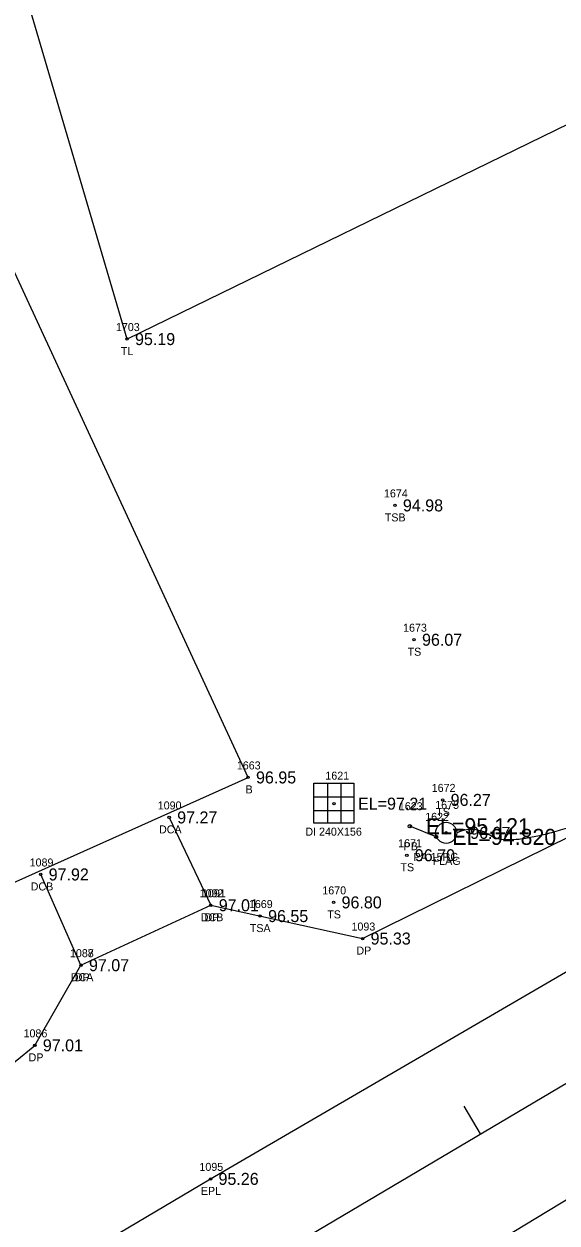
# Model space of a CAD drawing. Extents: x 2529517 to 2532038, y 935000 to 936944.
# Drawn here: x 2530845 to 2530911.6, y 935818.5 to 935968.4 of the extents above; entities that cross this region are included whole.
import ezdxf

# ---------------------------------------------------------------- set-up
doc = ezdxf.new("R2010")
doc.units = 0
for name, color, linetype in [('Default', 7, 'Continuous'), ('RD_DTM_BkLn_txCode', 7, 'Continuous'), ('RD_EX_Bldg', 7, 'Continuous'), ('RD_EX_Bldg_txCode', 7, 'Continuous'), ('RD_EX_BldgApp', 7, 'Continuous'), ('RD_EX_BldgApp_txCode', 7, 'Continuous'), ('RD_EX_Conc', 7, 'Continuous'), ('RD_EX_Conc_txCode', 7, 'Continuous'), ('RD_EX_DR_Inlet', 7, 'Continuous'), ('RD_EX_DR_Inlet_txCode', 7, 'Continuous'), ('RD_EX_DR_Pipe', 7, 'Continuous'), ('RD_EX_DR_Pipe_txCode', 7, 'Continuous'), ('RD_EX_Driveway', 7, 'Continuous'), ('RD_EX_Driveway_txCode', 7, 'Continuous'), ('RD_EX_Road', 7, 'Continuous'), ('RD_EX_Road_txCode', 7, 'Continuous'), ('RD_EX_TX_Bldg_ELEV', 7, 'Continuous'), ('RD_EX_TX_BldgApp_ELEV', 7, 'Continuous'), ('RD_EX_TX_Conc_ELEV', 7, 'Continuous'), ('RD_EX_TX_DR_Inlet_ELEV', 7, 'Continuous'), ('RD_EX_TX_Driveway_ELEV', 7, 'Continuous'), ('RD_EX_TX_Misc_ELEV', 7, 'Continuous'), ('RD_EX_TX_Road_ELEV', 7, 'Continuous'), ('RD_EX_TX_VEG_ELEV', 7, 'Continuous'), ('RD_EX_VEG', 7, 'Continuous'), ('RD_EX_VEG_txCode', 7, 'Continuous'), ('RD_HC_Cl', 7, 'Continuous'), ('RD_HC_Data_Tic', 7, 'Continuous'), ('RD_SMD_Locator', 7, 'Continuous'), ('RD_TX_Pipe_ElevEX', 7, 'Continuous')]:
    doc.layers.add(name, color=color, linetype=linetype)

msp = doc.modelspace()

# ---------------------------------------------------------------- linework, layer by layer
at = {"layer": 'Default'}
msp.add_line((2530557.05, 935625.34), (2531768.07, 936342.55), dxfattribs=at)
at = {"layer": 'RD_EX_Bldg'}
msp.add_lwpolyline([(2530770.25, 935914.58), (2530813.66, 935823.56), (2530836.66, 935835.13), (2530828.22, 935854.14), (2530872.98, 935874.21), (2530837.66, 935950.51), (2530770.25, 935914.58)], dxfattribs=at)
at = {"layer": 'RD_EX_BldgApp'}
for radius in [1.32, 0.15]:
    msp.add_circle((2530897.76, 935867.28), radius, dxfattribs=at)
msp.add_open_spline([(2530899.08, 935867.28), (2530901.09, 935868.38), (2530905.77, 935865.43), (2530915.13, 935868.61)], degree=2, dxfattribs=at)
at = {"layer": 'RD_EX_Conc'}
for p, q in [((2530863.12, 935869.21), (2530868.32, 935858.23)), ((2530852.09, 935850.74), (2530847.05, 935862.08))]:
    msp.add_line(p, q, dxfattribs=at)
at = {"layer": 'RD_EX_DR_Inlet'}
for p, q in [((2530882.9, 935873.49), (2530882.9, 935868.49)), ((2530884.6, 935873.49), (2530884.6, 935868.49)), ((2530881.2, 935871.79), (2530886.2, 935871.79)), ((2530881.2, 935870.09), (2530886.2, 935870.09))]:
    msp.add_line(p, q, dxfattribs=at)
msp.add_lwpolyline([(2530881.2, 935868.49), (2530881.2, 935873.49), (2530886.2, 935873.49), (2530886.2, 935868.49)], close=True, dxfattribs=at)
at = {"layer": 'RD_EX_DR_Pipe'}
msp.add_line((2530896.51, 935866.78), (2530893.21, 935868.11), dxfattribs=at)
at = {"layer": 'RD_EX_Driveway'}
msp.add_lwpolyline([(2530835.18, 935834.1), (2530836.46, 935832.71), (2530846.32, 935840.72), (2530852.09, 935850.74), (2530868.32, 935858.23), (2530887.31, 935854.07), (2530913.36, 935866.89), (2530921.11, 935858.25), (2530924.84, 935856.95)], dxfattribs=at)
at = {"layer": 'RD_EX_Road'}
for points in [[(2530213.13, 935600.16), (2530313.8, 935600.81), (2530414.15, 935601.13), (2530426.72, 935601.43), (2530429.46, 935603.55), (2530467.67, 935608.62), (2530486.46, 935612.38), (2530518.02, 935622.55), (2530522.16, 935623.68), (2530567.91, 935646.01), (2530609.3, 935670.15), (2530695.46, 935720.02), (2530775.85, 935769.27), (2530868.29, 935824.03), (2530924.84, 935856.95), (2530956.21, 935875.82), (2531040.72, 935926.38), (2531079.45, 935947.76)], [(2530212.44, 935579.72), (2530312.61, 935580.14), (2530402.98, 935580.64), (2530451.06, 935579.53), (2530466.91, 935580.35), (2530487.45, 935583.29), (2530533.43, 935598.45), (2530580.28, 935625.08), (2530621.69, 935649.23), (2530704.62, 935698.35), (2530718.67, 935706.38), (2530795.45, 935752.36), (2530871.33, 935796.67), (2530882.4, 935803.04), (2530947.17, 935842.26), (2530966, 935852.42), (2530992.72, 935868), (2531009.49, 935879.01), (2531052.39, 935904.85), (2531090.88, 935928.23)]]:
    msp.add_lwpolyline(points, dxfattribs=at)
at = {"layer": 'RD_EX_VEG'}
msp.add_lwpolyline([(2531065.97, 935956.74), (2531029.72, 936036.27), (2530913.11, 935955.89), (2530857.85, 935929), (2530845.59, 935970.77)], dxfattribs=at)
at = {"layer": 'RD_HC_Cl'}
msp.add_line((2530557.05, 935625.34), (2531768.07, 936342.55), dxfattribs=at)
at = {"layer": 'RD_HC_Data_Tic'}
msp.add_line((2530902.07, 935829.68), (2530900.03, 935833.12), dxfattribs=at)
at = {"layer": 'RD_SMD_Locator'}
for centre, radius in [((2530857.85, 935929), 0.15), ((2530891.35, 935908.21), 0.15), ((2530893.74, 935891.42), 0.15), ((2530872.98, 935874.21), 0.15), ((2530897.32, 935871.4), 0.15), ((2530883.74, 935870.93), 0.15), ((2530863.12, 935869.21), 0.15), ((2530893.21, 935868.11), 0.2), ((2530896.51, 935866.78), 0.2), ((2530892.84, 935864.48), 0.15), ((2530847.05, 935862.08), 0.15), ((2530868.32, 935858.23), 0.15), ((2530868.32, 935858.23), 0.15), ((2530883.68, 935858.59), 0.15), ((2530874.49, 935856.88), 0.15), ((2530887.31, 935854.07), 0.15), ((2530852.09, 935850.74), 0.15), ((2530852.09, 935850.74), 0.15), ((2530846.32, 935840.72), 0.15), ((2530868.29, 935824.03), 0.15)]:
    msp.add_circle(centre, radius, dxfattribs=at)

# ---------------------------------------------------------------- texts
at = {"layer": 'RD_DTM_BkLn_txCode'}
for s, p in [('1674', (2530889.98, 935909.21)), ('TSB', (2530890.08, 935906.21)), ('1673', (2530892.37, 935892.42)), ('TS', (2530892.94, 935889.42)), ('1672', (2530895.95, 935872.4)), ('TS', (2530896.52, 935869.4)), ('1671', (2530891.75, 935865.48)), ('TS', (2530892.04, 935862.48)), ('1670', (2530882.27, 935859.59)), ('1669', (2530873.09, 935857.88)), ('TS', (2530882.89, 935856.59)), ('TSA', (2530873.2, 935854.88))]:
    msp.add_text(s, height=1, dxfattribs=at).set_placement(p)
at = {"layer": 'RD_EX_Bldg_txCode'}
for s, p in [('1663', (2530871.58, 935875.21)), ('B', (2530872.67, 935872.21))]:
    msp.add_text(s, height=1, dxfattribs=at).set_placement(p)
at = {"layer": 'RD_EX_BldgApp_txCode'}
for s, p in [('1675', (2530896.39, 935870.28)), ('FLAG', (2530896.07, 935863.28))]:
    msp.add_text(s, height=1, dxfattribs=at).set_placement(p)
at = {"layer": 'RD_EX_Conc_txCode'}
for s, p in [('1090', (2530861.69, 935870.21)), ('DCA', (2530861.85, 935867.21)), ('1089', (2530845.67, 935863.08)), ('DCB', (2530845.8, 935860.08)), ('1091', (2530867.22, 935859.23)), ('DCB', (2530867.07, 935856.23)), ('1088', (2530850.71, 935851.74)), ('DCA', (2530850.82, 935848.74))]:
    msp.add_text(s, height=1, dxfattribs=at).set_placement(p)
at = {"layer": 'RD_EX_DR_Inlet_txCode'}
for s, p in [('1621', (2530882.65, 935873.93)), ('DI 240X156', (2530880.15, 935866.93))]:
    msp.add_text(s, height=1, dxfattribs=at).set_placement(p)
at = {"layer": 'RD_EX_DR_Pipe_txCode'}
for s, p in [('1623', (2530891.84, 935870.11)), ('1622', (2530895.14, 935868.78)), ('PB', (2530892.43, 935865.11)), ('PA 15RC', (2530893.67, 935863.78))]:
    msp.add_text(s, height=1, dxfattribs=at).set_placement(p)
at = {"layer": 'RD_EX_Driveway_txCode'}
for s, p in [('1092', (2530866.93, 935859.23)), ('DP', (2530867.54, 935856.23)), ('1093', (2530885.92, 935855.07)), ('1087', (2530850.71, 935851.74)), ('DP', (2530886.53, 935852.07)), ('DP', (2530851.31, 935848.74)), ('1086', (2530844.91, 935841.72)), ('DP', (2530845.54, 935838.72))]:
    msp.add_text(s, height=1, dxfattribs=at).set_placement(p)
at = {"layer": 'RD_EX_Road_txCode'}
for s, p in [('1095', (2530866.9, 935825.03)), ('EPL', (2530867.08, 935822.03))]:
    msp.add_text(s, height=1, dxfattribs=at).set_placement(p)
at = {"layer": 'RD_EX_TX_Bldg_ELEV'}
msp.add_text('96.95', height=1.5, dxfattribs=at).set_placement((2530873.98, 935873.46))
at = {"layer": 'RD_EX_TX_BldgApp_ELEV'}
msp.add_text('96.07', height=1.5, dxfattribs=at).set_placement((2530900.76, 935866.53))
at = {"layer": 'RD_EX_TX_Conc_ELEV'}
for s, p in [('97.27', (2530864.12, 935868.46)), ('97.92', (2530848.05, 935861.33)), ('97.01', (2530869.32, 935857.48)), ('97.07', (2530853.09, 935849.99))]:
    msp.add_text(s, height=1.5, dxfattribs=at).set_placement(p)
at = {"layer": 'RD_EX_TX_DR_Inlet_ELEV'}
msp.add_text('EL=97.21', height=1.5, dxfattribs=at).set_placement((2530886.74, 935870.18))
at = {"layer": 'RD_EX_TX_Driveway_ELEV'}
for s, p in [('97.01', (2530869.32, 935857.48)), ('95.33', (2530888.31, 935853.32)), ('97.07', (2530853.09, 935849.99)), ('97.01', (2530847.32, 935839.97))]:
    msp.add_text(s, height=1.5, dxfattribs=at).set_placement(p)
at = {"layer": 'RD_EX_TX_Misc_ELEV'}
for s, p in [('94.98', (2530892.35, 935907.46)), ('96.07', (2530894.74, 935890.67)), ('96.27', (2530898.32, 935870.65)), ('96.70', (2530893.84, 935863.73)), ('96.80', (2530884.68, 935857.84)), ('96.55', (2530875.49, 935856.13))]:
    msp.add_text(s, height=1.5, dxfattribs=at).set_placement(p)
at = {"layer": 'RD_EX_TX_Road_ELEV'}
msp.add_text('95.26', height=1.5, dxfattribs=at).set_placement((2530869.29, 935823.28))
at = {"layer": 'RD_EX_TX_VEG_ELEV'}
msp.add_text('95.19', height=1.5, dxfattribs=at).set_placement((2530858.85, 935928.25))
at = {"layer": 'RD_EX_VEG_txCode'}
for s, p in [('1703', (2530856.46, 935930)), ('TL', (2530857.08, 935927))]:
    msp.add_text(s, height=1, dxfattribs=at).set_placement(p)
at = {"layer": 'RD_TX_Pipe_ElevEX'}
for s, p in [('EL=95.121', (2530895.21, 935867.11)), ('EL=94.820', (2530898.51, 935865.78))]:
    msp.add_text(s, height=2, dxfattribs=at).set_placement(p)

doc.saveas('drawing.dxf')
